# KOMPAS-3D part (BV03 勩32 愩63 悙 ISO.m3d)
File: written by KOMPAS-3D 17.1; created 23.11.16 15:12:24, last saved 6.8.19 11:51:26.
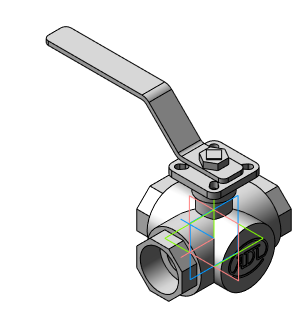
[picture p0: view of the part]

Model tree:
1. Операция без истории:1  (labels: Сталь 20  ГОСТ 1050-88)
